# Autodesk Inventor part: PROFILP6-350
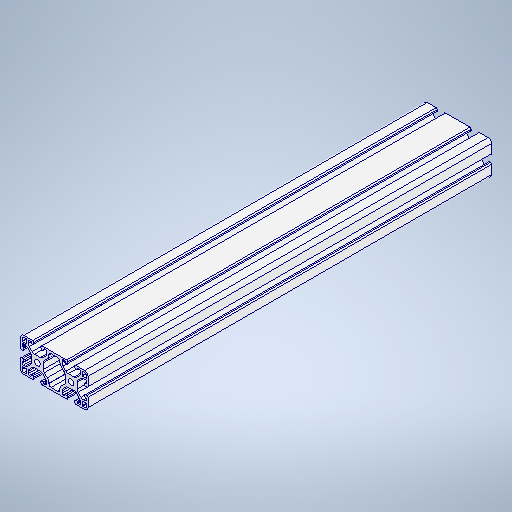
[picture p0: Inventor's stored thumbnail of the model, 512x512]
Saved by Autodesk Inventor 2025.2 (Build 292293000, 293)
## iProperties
Created: 2017-03
Part Number: PROFILP6-350
Material: Generic
Description: Aluminium eloxiert RAL 9006
Document SubType Name: Modeling
Designer: Jarni
Density: 1 g/cm^3
Appearance: Default
Sending System: Autodesk Inventor 2015
Preprocessor: ST-DEVELOPER v15.6
Title: C:\Users\Public\VaultWorkspace\Designs\Katalogteile\P6-60x30-L\P6-60x30-L.stp
Author: dt
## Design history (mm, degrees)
node "Volumenkörper1"
thicken "Thicken1" dims "d0" = 2, "d1" = 2
body "Solid1"
